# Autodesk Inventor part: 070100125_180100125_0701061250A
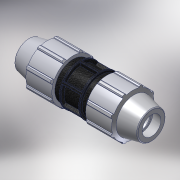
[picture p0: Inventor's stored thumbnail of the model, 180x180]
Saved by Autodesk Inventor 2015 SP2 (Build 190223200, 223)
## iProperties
Created: 2017-02
Part Number: 070100125_180100125_0701061250A
Material: PVC-Piping
Description: PLASSON COUPLER 125-125
Document SubType Name: Modeling
Designer: KIM
Mass: 92.6774 g
Surface Area: 199.44 cm^2
Volume: 66.1981 cm^3
Density: 1.4 g/cm^3
Appearance: PTFE
Author: KIM
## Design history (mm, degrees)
derived "07010.ipt"
feature "Solid1::07010.ipt"
tag "TaggingFeature1"
body "Solid1"
other parameters: "d2" = 125, "d4" = 38.33333, "d5" = 65.71429, "d7" = 212, "d8" = 159, "d9" = 65.71429, "d11" = 6.57143, "d12" = 169.6, "d13" = 120 deg, "d14" = 162.5, "d15" = 6 deg, "d16" = 190.8, "d18" = 6.25, "d19" = 35 deg, "d20" = 17.5 deg, "d21" = 197.16, "d23" = 0, "d25" = 360 deg, "d27" = 4.24, "d33" = 2.5, "d34" = 10.6, "d36" = 0, "d37" = 2.5, "d38" = 2.5, "d40" = 360 deg, "d42" = 101.2, "d43" = 6.36, "d46" = 3.75, "d49" = 225, "d_" = 125, "E_" = 212, "l_" = 225
